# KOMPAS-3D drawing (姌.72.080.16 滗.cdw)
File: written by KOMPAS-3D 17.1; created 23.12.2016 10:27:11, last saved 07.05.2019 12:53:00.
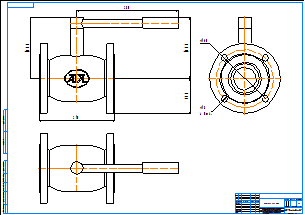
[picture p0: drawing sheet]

Sheet 1: A1, landscape

Title block, sheet 1: name: КШ.72.080.16 фф; material: Внимание! Данный продукт является объектом авторского права ООО «Торговый Дом АДЛ». / Запрещается изменение, копирование, распространение / (в том числе путем копирования на другие сайты и ресурсы в Интернете) / или любое иное использование информации и объектов без предварительного / согласия правообладателя (ООО «Торговый Дом АДЛ»).; sheets: 1; organisation: ООО "Торговый дом АДЛ"; sheet format: A1; stored path: C:\Users\tra\Desktop\2д чертежи\Шаровые краны БИВАЛ\КШ_Бивал_серия_72\KOMPAS_2D\КШ.72.080.16 фф.cdw

Views: Спереди 4, Проекционный вид 5, Проекционный вид 6
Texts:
  Klimkovich
  ADL
Dimensions and other numbers on the sheet: 210; 280; 168,8; 97,5; 160; 18; 4 Отв.; 1:1; 1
